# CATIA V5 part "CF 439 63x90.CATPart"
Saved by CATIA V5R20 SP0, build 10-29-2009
Part number: CF 439 63x90
Definition: NONE
Nomenclature: CF 439 63x90
Source: Unknown
Description: CF 439 63x90
Bounding box of the stored display mesh (mm): x -46 to 46, y 0 to 90, z -46 to 46
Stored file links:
  C:\Users\Utente\Desktop\IO LAVORO\3D X SITO CF\X SITO\CF 439\CF 439 63x90.CATPart
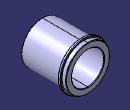
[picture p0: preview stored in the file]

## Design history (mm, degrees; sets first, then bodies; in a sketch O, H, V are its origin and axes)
Body1 "CF 439 63x90" (main body)
  Solid1: solid without history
